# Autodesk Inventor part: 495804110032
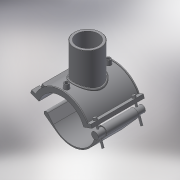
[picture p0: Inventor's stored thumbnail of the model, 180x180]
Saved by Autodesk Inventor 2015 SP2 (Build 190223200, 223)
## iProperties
Created: 2017-07
Part Number: 495804110032
Material: Generic
Description: PLASSON BRANCH SADDLE 110-32
Document SubType Name: Modeling
Designer: KIM
Density: 1 g/cm^3
Appearance: Default
Author: KIM
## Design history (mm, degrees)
derived "495804.ipt"
feature "Solid1::495804.ipt"
feature "Solid2::495804.ipt"
tag "TaggingFeature1"
body "Solid1"
body "Solid2"
other parameters: "d2" = 148, "d3" = 27.5, "d4" = 118, "d5" = 0, "d6" = 0.1, "d8" = 0, "d19" = 6, "d20" = 6, "d21" = 70.8, "d23" = 0, "d24" = 35.4, "d26" = 0, "d27" = 3, "d28" = 3, "d29" = 3, "d30" = 36.66667, "d31" = 6, "d32" = 0, "d33" = 0, "d34" = 0.6, "d40" = 67.6, "d41" = 35.2, "d43" = 0, "d45" = 0, "d47" = 124, "d48" = 32, "d50" = 0, "d70" = 15, "d72" = 0, "d73" = 6, "d75" = 5, "d76" = 0, "d77" = 5.5, "d78" = 85, "d79" = 15, "d80" = 47.2, "d82" = 5 deg, "d84" = 4, "d85" = 14, "d86" = 0, "d87" = 3, "d88" = 0, "d89" = 1, "d90" = 1, "d91" = 94.4, "d92" = 0, "d93" = 0.5, "d94" = 57.89474, "d96" = 132.6, "d97" = 2.36, "d98" = 0, "d102" = 0.96, "d103" = 25.6, "d105" = 0, "d109" = -19.66667, "d117" = 0.32, "d120" = 140 deg, "d121" = 24.228, "d122" = 20 deg, "d124" = 78, "d126" = 0, "d143" = 115.5, "d150" = 19.8, "d159" = 4, "d161" = 2.75, "d162" = 70.8, "d163" = 0, "d167" = 22, "d168" = 59.09091, "d173" = 1, "d175" = 55, "d176" = 20 deg, "d177" = 7.7, "d180" = 0, "d185" = 38.35, "d186" = 38.35, "d187" = 65, "d188" = 6, "d189" = 7.7, "d190" = 0, "d191" = 97.5, "d202" = 0, "d216" = 106.2, "d217" = 0, "d221" = 43.66, "d222" = 7.7, "d223" = 4.62, "d224" = 55, "d225" = 4.62, "d227" = 15.84, "d230" = 68.2, "d236" = 20 deg, "d237" = 72, "d238" = 20 deg, "d239" = 7.7, "B_" = 148, "H_" = 59, "L_" = 118, "d_t" = 6, "d_1" = 32, "H_1" = 49, "d148" = 2.75, "d160" = 2.75
